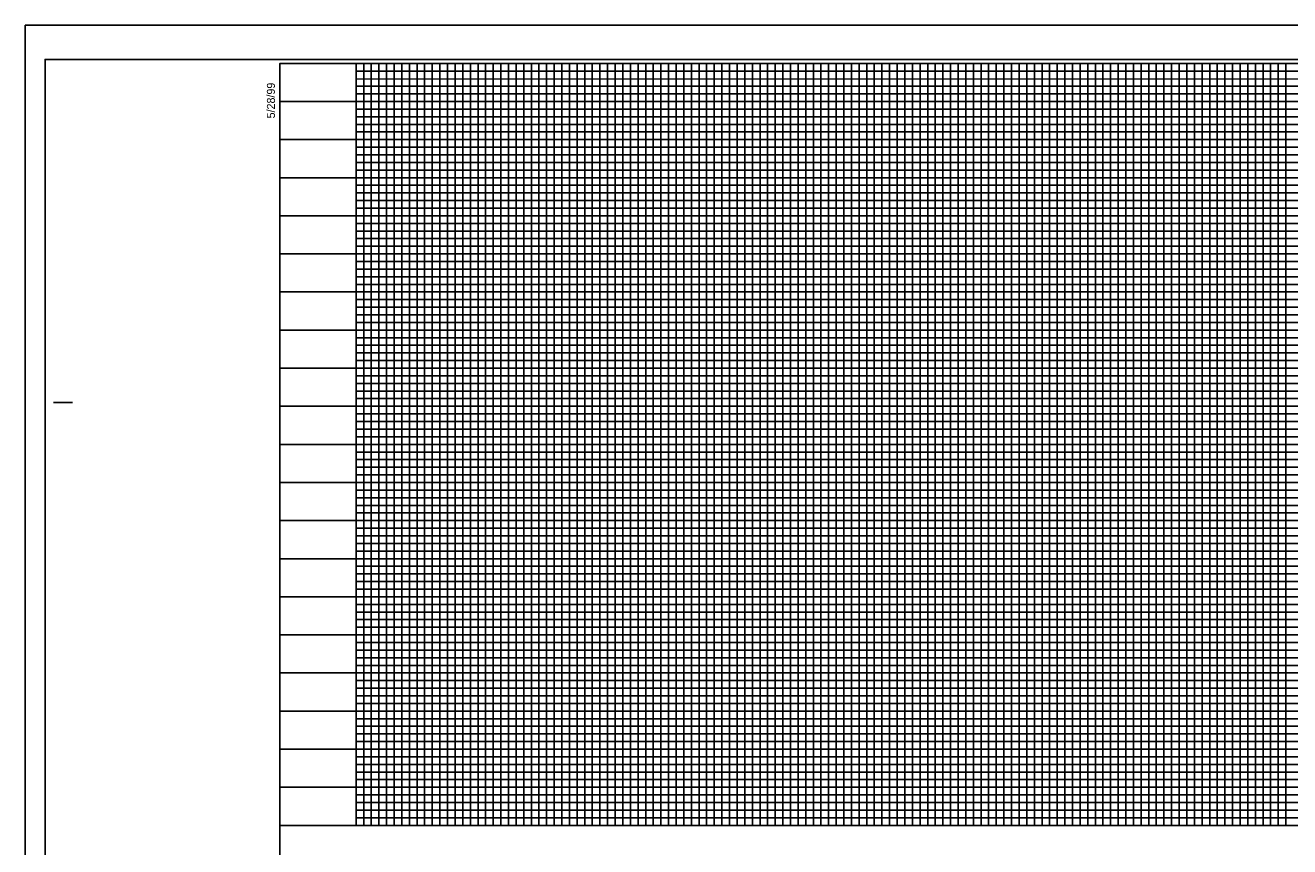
# Model space of a CAD drawing. Extents: x 2044835 to 2046519, y 755505 to 756605.
# Drawn here: x 2044835 to 2045664, y 756066 to 756605 of the extents above; entities that cross this region are included whole.
import ezdxf

# ---------------------------------------------------------------- set-up
doc = ezdxf.new("R2010")
doc.units = 0
for name, color, linetype in [('Sheet Cutting Line CELL', 7, 'Continuous'), ('Sheet DOT Grid CELL', 7, 'Continuous'), ('Sheet Layout Profile Border Port 1', 7, 'Continuous'), ('Sheet Plot Border Inside CELL', 7, 'Continuous'), ('Sheet Plot Border Outside CELL', 7, 'Continuous'), ('Sheet Profile CELL', 7, 'Continuous'), ('Sheet Profile Grid Major CELL', 7, 'Continuous'), ('Sheet Profile Grid Middle CELL', 7, 'Continuous'), ('Sheet Profile Grid Minor CELL', 7, 'Continuous')]:
    doc.layers.add(name, color=color, linetype=linetype)

msp = doc.modelspace()

# ---------------------------------------------------------------- linework, layer by layer
at = {"layer": 'Sheet Cutting Line CELL'}
for p, q in [((2046518.63, 756605.41), (2044834.63, 756605.41)), ((2044834.63, 756605.41), (2044834.63, 755505.41))]:
    msp.add_line(p, q, dxfattribs=at)
at = {"layer": 'Sheet DOT Grid CELL'}
for p, q in [((2045051.63, 756080.41), (2045051.63, 756580.41)), ((2045101.63, 756080.41), (2045101.63, 756580.41)), ((2045151.63, 756080.41), (2045151.63, 756580.41)), ((2045201.63, 756080.41), (2045201.63, 756580.41)), ((2045251.63, 756080.41), (2045251.63, 756580.41)), ((2045301.63, 756080.41), (2045301.63, 756580.41)), ((2045351.63, 756080.41), (2045351.63, 756580.41)), ((2045401.63, 756080.41), (2045401.63, 756580.41)), ((2045451.63, 756080.41), (2045451.63, 756580.41)), ((2045501.63, 756080.41), (2045501.63, 756580.41)), ((2045551.63, 756080.41), (2045551.63, 756580.41)), ((2045601.63, 756080.41), (2045601.63, 756580.41)), ((2045651.63, 756080.41), (2045651.63, 756580.41)), ((2046101.63, 756530.41), (2045001.63, 756530.41)), ((2046301.58, 756480.41), (2045001.63, 756480.41)), ((2046301.63, 756430.41), (2045001.63, 756430.41)), ((2046501.63, 756380.41), (2045001.63, 756380.41)), ((2046501.63, 756330.41), (2045001.63, 756330.41)), ((2046501.63, 756280.41), (2045001.63, 756280.41)), ((2046501.63, 756230.41), (2045001.63, 756230.41)), ((2046501.63, 756180.41), (2045001.63, 756180.41)), ((2046501.63, 756130.41), (2045001.63, 756130.41))]:
    msp.add_line(p, q, dxfattribs=at)
at = {"layer": 'Sheet Layout Profile Border Port 1'}
msp.add_lwpolyline([(2045051.63, 756419.36), (2045051.63, 756080.41), (2046451.63, 756080.41), (2046451.63, 756419.36)], dxfattribs=at)
at = {"layer": 'Sheet Plot Border Inside CELL'}
msp.add_lwpolyline([(2044847.63, 755527.86), (2046514.13, 755527.86), (2046514.13, 756582.96), (2044847.63, 756582.96)], close=True, dxfattribs=at)
at = {"layer": 'Sheet Plot Border Outside CELL'}
msp.add_lwpolyline([(2044834.63, 755505.41), (2046518.63, 755505.41), (2046518.63, 756605.41), (2044834.63, 756605.41)], close=True, dxfattribs=at)
at = {"layer": 'Sheet Profile CELL'}
for p, q in [((2044853.13, 756357.91), (2044865.63, 756357.91)), ((2045001.63, 756080.41), (2046501.63, 756080.41))]:
    msp.add_line(p, q, dxfattribs=at)
msp.add_lwpolyline([(2046501.63, 756580.41), (2045001.63, 756580.41), (2045001.63, 755530.41), (2046501.63, 755530.41)], close=True, dxfattribs=at)
at = {"layer": 'Sheet Profile Grid Major CELL'}
for points in [[(2045051.63, 756580.41), (2045051.63, 756080.41), (2045101.63, 756080.41), (2045101.63, 756580.41), (2045151.63, 756580.41), (2045151.63, 756080.41), (2045201.63, 756080.41), (2045201.63, 756580.41), (2045251.63, 756580.41), (2045251.63, 756080.41), (2045301.63, 756080.41), (2045301.63, 756580.41), (2045351.63, 756580.41), (2045351.63, 756080.41), (2045401.63, 756080.41), (2045401.63, 756580.41), (2045451.63, 756580.41), (2045451.63, 756080.41), (2045501.63, 756080.41), (2045501.63, 756580.41), (2045551.63, 756580.41), (2045551.63, 756080.41), (2045601.63, 756080.41), (2045601.63, 756580.41), (2045651.63, 756580.41), (2045651.63, 756080.41), (2045701.63, 756080.41)], [(2045001.63, 756530.41), (2046101.63, 756530.41)], [(2046301.63, 756480.41), (2045001.63, 756480.41), (2045001.63, 756430.41), (2046301.63, 756430.41)], [(2046501.63, 756380.41), (2045001.63, 756380.41), (2045001.63, 756330.41), (2046501.63, 756330.41)], [(2046501.63, 756280.41), (2045001.63, 756280.41), (2045001.63, 756230.41), (2046501.63, 756230.41)], [(2046501.63, 756180.41), (2045001.63, 756180.41), (2045001.63, 756180.41), (2045001.63, 756130.41), (2046501.63, 756130.41)]]:
    msp.add_lwpolyline(points, dxfattribs=at)
at = {"layer": 'Sheet Profile Grid Middle CELL'}
for p, q in [((2045076.63, 756580.41), (2045076.63, 756080.41)), ((2045126.63, 756080.41), (2045126.63, 756580.41)), ((2045126.63, 756580.41), (2045176.63, 756580.41)), ((2045176.63, 756580.41), (2045176.63, 756080.41)), ((2045226.63, 756080.41), (2045226.63, 756580.41)), ((2045226.63, 756580.41), (2045276.63, 756580.41)), ((2045276.63, 756580.41), (2045276.63, 756080.41)), ((2045326.63, 756080.41), (2045326.63, 756580.41)), ((2045326.63, 756580.41), (2045376.63, 756580.41)), ((2045376.63, 756580.41), (2045376.63, 756080.41)), ((2045426.63, 756080.41), (2045426.63, 756580.41)), ((2045426.63, 756580.41), (2045476.63, 756580.41)), ((2045476.63, 756580.41), (2045476.63, 756080.41)), ((2045526.63, 756080.41), (2045526.63, 756580.41)), ((2045526.63, 756580.41), (2045576.63, 756580.41)), ((2045576.63, 756580.41), (2045576.63, 756080.41)), ((2045626.63, 756080.41), (2045626.63, 756580.41)), ((2045626.63, 756580.41), (2045676.63, 756580.41)), ((2045001.63, 756555.41), (2046101.63, 756555.41)), ((2045076.63, 756080.41), (2045126.63, 756080.41)), ((2045176.63, 756080.41), (2045226.63, 756080.41)), ((2045276.63, 756080.41), (2045326.63, 756080.41)), ((2045376.63, 756080.41), (2045426.63, 756080.41)), ((2045476.63, 756080.41), (2045526.63, 756080.41)), ((2045576.63, 756080.41), (2045626.63, 756080.41)), ((2045626.63, 756080.41), (2045626.63, 756080.41))]:
    msp.add_line(p, q, dxfattribs=at)
for points in [[(2046101.63, 756505.41), (2045001.63, 756505.41), (2045001.63, 756455.41), (2046301.63, 756455.41)], [(2046501.63, 756405.41), (2045001.63, 756405.41), (2045001.63, 756355.41), (2046326.63, 756355.41)], [(2046501.63, 756305.41), (2045001.63, 756305.41), (2045001.63, 756255.41), (2046501.63, 756255.41)], [(2046501.63, 756205.41), (2045001.63, 756205.41), (2045001.63, 756155.41), (2046501.63, 756155.41)], [(2046501.63, 756105.41), (2045001.63, 756105.41)]]:
    msp.add_lwpolyline(points, dxfattribs=at)
at = {"layer": 'Sheet Profile Grid Minor CELL'}
for p, q in [((2045051.63, 756575.41), (2046101.63, 756575.41)), ((2045051.63, 756570.41), (2045051.63, 756570.41)), ((2046101.63, 756570.36), (2045051.63, 756570.06)), ((2045051.63, 756565.41), (2046101.63, 756565.41)), ((2046101.63, 756560.41), (2045051.63, 756560.41)), ((2045051.63, 756560.41), (2045051.63, 756550.41)), ((2045051.63, 756550.41), (2046101.63, 756550.41)), ((2046301.63, 756460.41), (2045051.63, 756460.41)), ((2045051.63, 756460.41), (2045051.63, 756450.41)), ((2045051.63, 756450.41), (2046301.63, 756450.41)), ((2046301.58, 756445.41), (2045051.63, 756445.41)), ((2046301.63, 756440.41), (2045051.63, 756440.41)), ((2046301.63, 756435.41), (2045051.63, 756435.41)), ((2045051.63, 756425.41), (2046301.63, 756425.41)), ((2046301.63, 756420.41), (2045051.63, 756420.41)), ((2045051.63, 756415.41), (2046451.63, 756415.41)), ((2046451.63, 756395.41), (2045051.63, 756395.41)), ((2045051.63, 756390.41), (2046451.63, 756390.41)), ((2046451.63, 756370.41), (2045051.63, 756370.41)), ((2045051.63, 756365.41), (2046451.63, 756365.41)), ((2046451.63, 756345.41), (2045051.63, 756345.41)), ((2045051.63, 756340.41), (2046451.63, 756340.41)), ((2046451.63, 756335.41), (2045051.63, 756335.41)), ((2045051.63, 756325.41), (2046451.63, 756325.41)), ((2046451.63, 756320.41), (2045051.63, 756320.41)), ((2045051.63, 756315.41), (2046451.63, 756315.41)), ((2046451.63, 756310.41), (2045051.63, 756310.41)), ((2045051.63, 756300.41), (2046451.63, 756300.41)), ((2046451.63, 756295.41), (2045051.63, 756295.41)), ((2045051.63, 756290.41), (2046451.63, 756290.41)), ((2046451.63, 756285.41), (2045051.63, 756285.41)), ((2045051.63, 756275.41), (2046451.63, 756275.41)), ((2046451.63, 756270.41), (2045051.63, 756270.41)), ((2045051.63, 756265.41), (2046451.63, 756265.41)), ((2046451.63, 756260.41), (2045051.63, 756260.41)), ((2045051.63, 756250.41), (2046451.63, 756250.41)), ((2046451.63, 756245.41), (2045051.63, 756245.41)), ((2045051.63, 756240.41), (2046451.63, 756240.41)), ((2046451.63, 756235.41), (2045051.63, 756235.41)), ((2045051.63, 756225.41), (2046451.63, 756225.41)), ((2046451.63, 756220.41), (2045051.63, 756220.41)), ((2045051.63, 756215.41), (2046451.63, 756215.41)), ((2046451.63, 756210.41), (2045051.63, 756210.41)), ((2045051.63, 756200.41), (2046451.63, 756200.41)), ((2046451.63, 756195.41), (2045051.63, 756195.41)), ((2046451.63, 756190.41), (2045051.63, 756190.41)), ((2046451.63, 756185.41), (2045051.63, 756185.41)), ((2045051.63, 756175.41), (2046451.63, 756175.41)), ((2046451.63, 756170.41), (2045051.63, 756170.41)), ((2045051.63, 756165.41), (2046451.63, 756165.41)), ((2046451.63, 756160.41), (2045051.63, 756160.41)), ((2045051.63, 756150.41), (2046451.63, 756150.41)), ((2046451.63, 756145.41), (2045051.63, 756145.41)), ((2045051.63, 756140.41), (2046451.63, 756140.41)), ((2046451.63, 756135.41), (2045051.63, 756135.41)), ((2045051.63, 756125.41), (2046451.63, 756125.41)), ((2046451.63, 756120.41), (2045051.63, 756120.41)), ((2045051.63, 756115.41), (2046451.63, 756115.41)), ((2046451.63, 756110.41), (2045051.63, 756110.41)), ((2045051.63, 756100.41), (2046451.63, 756100.41)), ((2046451.63, 756095.41), (2045051.63, 756095.41)), ((2045051.63, 756090.41), (2046451.63, 756090.41))]:
    msp.add_line(p, q, dxfattribs=at)
for points in [[(2045056.63, 756580.41), (2045056.63, 756080.41), (2045061.63, 756080.41), (2045061.63, 756580.41), (2045066.63, 756580.41), (2045066.63, 756080.41), (2045071.63, 756080.41), (2045071.63, 756580.41), (2045081.63, 756580.41), (2045081.63, 756080.41), (2045086.63, 756080.41), (2045086.63, 756580.41), (2045091.63, 756580.41), (2045091.63, 756080.41), (2045096.63, 756080.41), (2045106.63, 756080.41), (2045111.63, 756080.41), (2045111.63, 756580.41), (2045116.63, 756580.41), (2045116.63, 756080.41), (2045121.63, 756080.41), (2045121.63, 756580.41), (2045131.63, 756580.41), (2045131.63, 756080.41), (2045136.63, 756080.41), (2045136.63, 756580.41), (2045141.63, 756580.41), (2045141.63, 756080.41), (2045146.63, 756080.41), (2045146.63, 756580.41), (2045156.63, 756580.41), (2045156.63, 756080.41), (2045161.63, 756080.41), (2045161.63, 756580.41), (2045166.63, 756580.41), (2045166.63, 756080.41), (2045171.63, 756080.41), (2045171.63, 756580.41), (2045181.63, 756580.41), (2045181.63, 756080.41), (2045186.63, 756080.41), (2045186.63, 756580.41), (2045191.63, 756580.41), (2045191.63, 756080.41), (2045196.63, 756080.41), (2045196.63, 756580.41), (2045206.63, 756580.41), (2045206.63, 756080.41), (2045211.63, 756080.41), (2045211.63, 756580.41), (2045216.63, 756580.41), (2045216.63, 756080.41), (2045221.63, 756080.41), (2045221.63, 756580.41), (2045231.63, 756580.41), (2045231.63, 756080.41), (2045236.63, 756080.41), (2045236.63, 756580.41), (2045241.63, 756580.41), (2045241.63, 756080.41), (2045246.63, 756080.41), (2045246.63, 756580.41), (2045256.63, 756580.41), (2045256.63, 756080.41), (2045261.63, 756080.41), (2045261.63, 756580.41), (2045266.63, 756580.41), (2045266.63, 756080.41)], [(2045096.63, 756080.41), (2045096.63, 756580.41), (2045106.63, 756580.41), (2045106.63, 756080.41)], [(2045266.63, 756080.41), (2045271.63, 756080.41), (2045271.63, 756580.41), (2045281.63, 756580.41), (2045281.63, 756080.41), (2045286.63, 756080.41), (2045286.63, 756580.41), (2045291.63, 756580.41), (2045291.63, 756080.41), (2045296.63, 756080.41), (2045296.63, 756580.41), (2045306.63, 756580.41), (2045306.63, 756080.41), (2045311.63, 756080.41), (2045311.63, 756580.41), (2045316.63, 756580.41), (2045316.63, 756080.41), (2045321.63, 756080.41), (2045321.63, 756580.41), (2045331.63, 756580.41), (2045331.63, 756080.41), (2045336.63, 756080.41), (2045336.63, 756580.41), (2045341.63, 756580.41), (2045341.63, 756080.41), (2045346.63, 756080.41), (2045346.63, 756580.41), (2045356.63, 756580.41), (2045356.63, 756080.41), (2045361.63, 756080.41), (2045361.63, 756580.41), (2045366.63, 756580.41), (2045366.63, 756080.41), (2045371.63, 756080.41), (2045371.63, 756580.41), (2045381.63, 756580.41), (2045381.63, 756080.41), (2045386.63, 756080.41), (2045386.63, 756580.41), (2045391.63, 756580.41), (2045391.63, 756080.41), (2045396.63, 756080.41), (2045396.63, 756580.41), (2045406.63, 756580.41), (2045406.63, 756080.41), (2045411.63, 756080.41), (2045411.63, 756580.41), (2045416.63, 756580.41), (2045416.63, 756080.41), (2045421.63, 756080.41), (2045421.63, 756580.41), (2045431.63, 756580.41), (2045431.63, 756080.41), (2045436.63, 756080.41), (2045436.63, 756580.41), (2045441.63, 756580.41), (2045441.63, 756080.41), (2045446.63, 756080.41), (2045446.63, 756580.41), (2045456.63, 756580.41), (2045456.63, 756080.41), (2045461.63, 756080.41), (2045461.63, 756580.41), (2045466.63, 756580.41), (2045466.63, 756080.41), (2045471.63, 756080.41), (2045471.63, 756580.41), (2045481.63, 756580.41), (2045481.63, 756080.41), (2045486.63, 756080.41), (2045486.63, 756580.41), (2045491.63, 756580.41), (2045491.63, 756080.41), (2045496.63, 756080.41), (2045496.63, 756580.41), (2045506.63, 756580.41), (2045506.63, 756080.41), (2045511.63, 756080.41), (2045511.63, 756580.41), (2045516.63, 756580.41), (2045516.63, 756080.41), (2045521.63, 756080.41), (2045521.63, 756580.41), (2045531.63, 756580.41), (2045531.63, 756080.41), (2045536.63, 756080.41), (2045536.63, 756580.41), (2045541.63, 756580.41), (2045541.63, 756080.41), (2045546.63, 756080.41), (2045546.63, 756580.41), (2045556.63, 756580.41), (2045556.63, 756080.41), (2045561.63, 756080.41), (2045561.63, 756580.41), (2045566.63, 756580.41), (2045566.63, 756080.41), (2045571.63, 756080.41), (2045571.63, 756580.41), (2045581.63, 756580.41)], [(2045581.63, 756580.41), (2045581.63, 756080.41), (2045586.63, 756080.41), (2045586.63, 756580.41), (2045591.63, 756580.41), (2045591.63, 756080.41), (2045596.63, 756080.41), (2045596.63, 756580.41), (2045606.63, 756580.41), (2045606.63, 756080.41), (2045611.63, 756080.41), (2045611.63, 756580.41), (2045616.63, 756580.41), (2045616.63, 756080.41), (2045621.63, 756080.41), (2045621.63, 756580.41), (2045631.63, 756580.41), (2045631.63, 756080.41), (2045636.63, 756080.41), (2045636.63, 756580.41), (2045641.63, 756580.41), (2045641.63, 756080.41), (2045646.63, 756080.41), (2045646.63, 756580.41), (2045656.63, 756580.41), (2045656.63, 756080.41), (2045661.63, 756080.41), (2045661.63, 756580.41), (2045666.63, 756580.41)], [(2046101.63, 756545.41), (2045051.63, 756545.41), (2045051.63, 756540.41), (2046101.63, 756540.41)], [(2046101.63, 756535.41), (2045051.63, 756535.41), (2045051.63, 756525.41), (2046101.63, 756525.41)], [(2046101.63, 756520.41), (2045051.63, 756520.41), (2045051.63, 756515.41), (2046101.63, 756515.41)], [(2046101.63, 756510.41), (2045051.63, 756510.41), (2045051.63, 756500.41), (2046101.63, 756500.41)], [(2046101.63, 756495.41), (2045051.63, 756495.41), (2045051.63, 756490.41), (2046101.63, 756490.41)], [(2046101.63, 756485.41), (2045051.63, 756485.41), (2045051.63, 756475.41), (2046301.63, 756475.41)], [(2046301.63, 756470.31), (2045051.73, 756470.31), (2045051.73, 756465.41), (2046301.63, 756465.41)], [(2046451.63, 756410.41), (2045051.63, 756410.41), (2045051.63, 756400.41), (2046451.63, 756400.41)], [(2046451.63, 756385.41), (2045051.63, 756385.41), (2045051.63, 756375.41), (2046451.63, 756375.41)], [(2046451.63, 756360.41), (2045051.63, 756360.41), (2045051.63, 756350.41), (2046451.63, 756350.41)], [(2046451.63, 756085.41), (2045051.63, 756085.41)]]:
    msp.add_lwpolyline(points, dxfattribs=at)

# ---------------------------------------------------------------- texts
at = {"layer": 'Sheet Profile CELL'}
msp.add_text('5/28/99', height=5.25, rotation=90, dxfattribs=at).set_placement((2044998.4, 756544.32))

doc.saveas('drawing.dxf')
